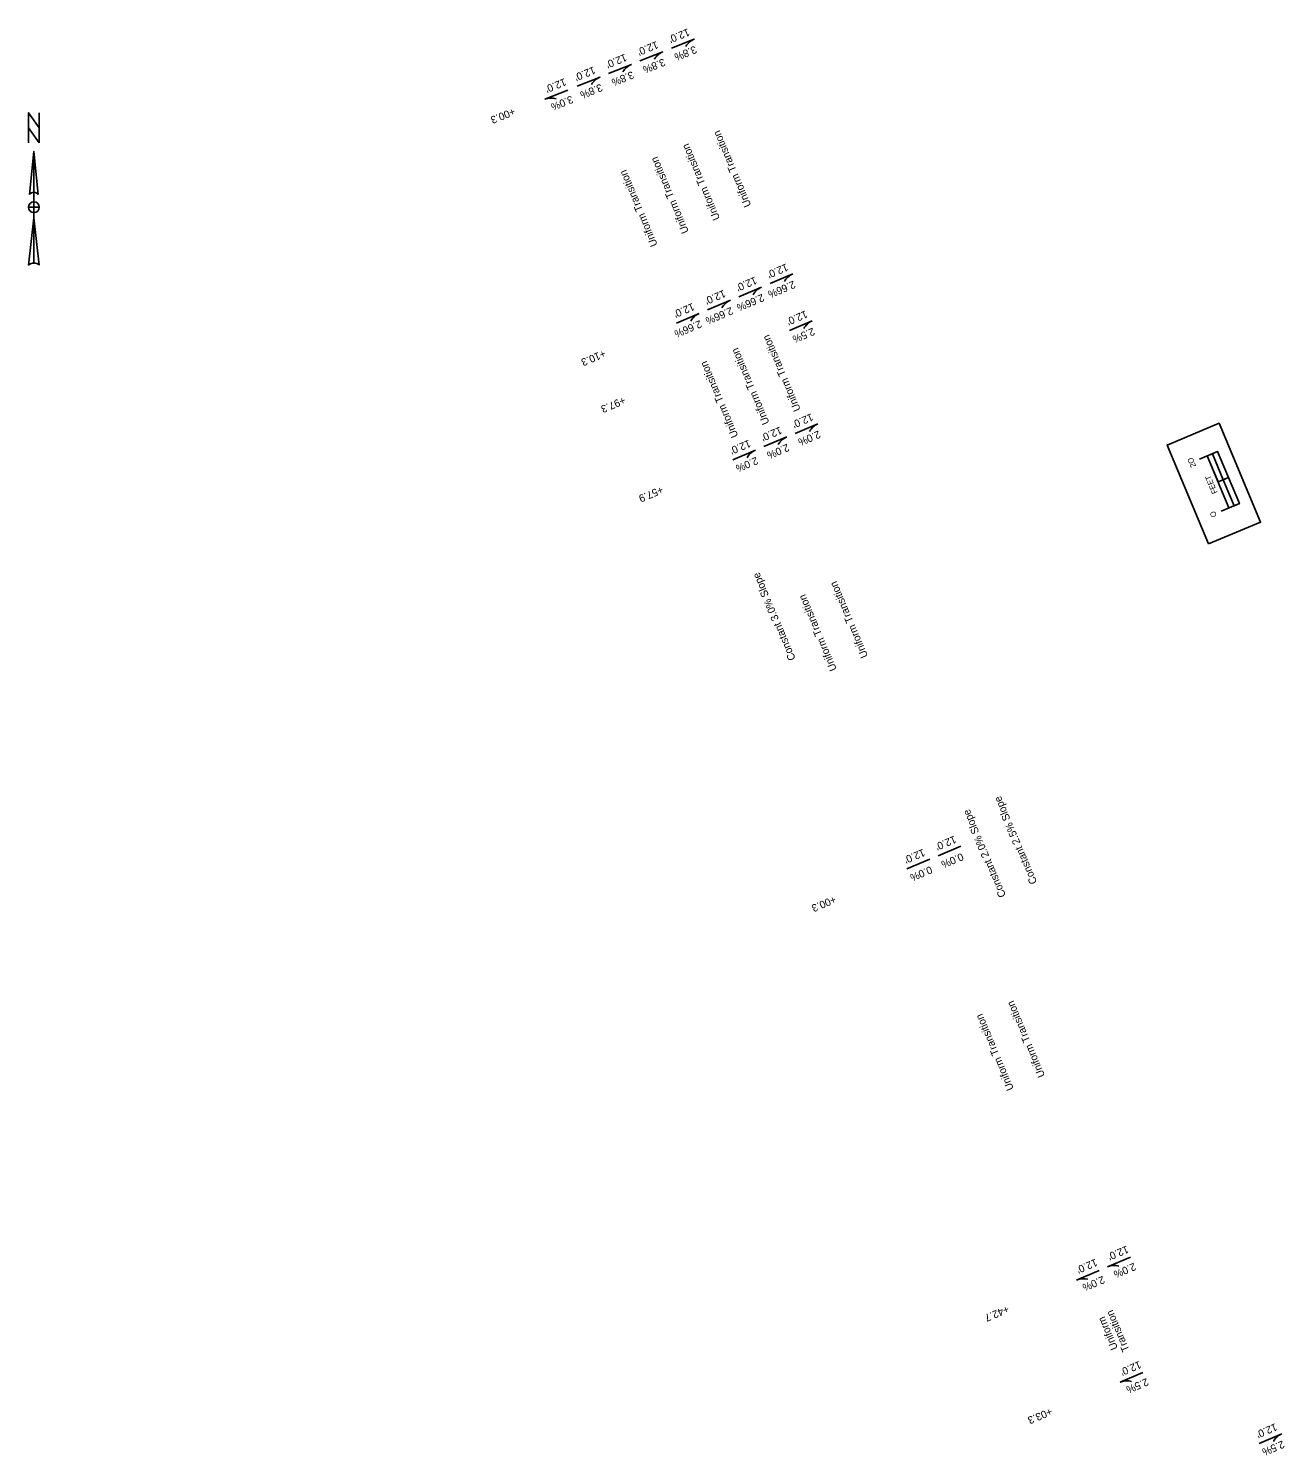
# Model space of a CAD drawing. Extents: x 20505195 to 20506806, y 7965197 to 7979043.
# Drawn here: x 20505639 to 20506084, y 7975959 to 7976464 of the extents above; entities that cross this region are included whole.
import ezdxf

# ---------------------------------------------------------------- set-up
doc = ezdxf.new("R2010")
doc.units = 0
doc.layers.add('Cell', color=7, linetype='Continuous')
doc.layers.add('SheetText', color=7, linetype='Continuous')

msp = doc.modelspace()

# ---------------------------------------------------------------- linework, layer by layer
at = {"layer": 'Cell'}
for p, q in [((20505641.01, 7976420.72), (20505642.53, 7976405.5)), ((20505641.01, 7976420.72), (20505641.01, 7976381.16)), ((20505639.49, 7976405.5), (20505639.49, 7976405.5)), ((20505639.54, 7976405.65), (20505639.83, 7976405.96)), ((20505639.11, 7976380.4), (20505641.01, 7976397.14)), ((20505641.01, 7976399.04), (20505641.01, 7976399.04))]:
    msp.add_line(p, q, dxfattribs=at)
msp.add_lwpolyline([(20505642.91, 7976423.76), (20505639.11, 7976429.08), (20505639.11, 7976434.41), (20505642.91, 7976429.08)], close=True, dxfattribs=at)
for points in [[(20505639.11, 7976423.76), (20505639.11, 7976434.41), (20505642.91, 7976429.08), (20505642.91, 7976434.41)], [(20505639.49, 7976405.5), (20505641.01, 7976420.72), (20505641.01, 7976406.27)], [(20505642.91, 7976400.94), (20505641.01, 7976400.94), (20505641.01, 7976402.84)], [(20505641.01, 7976399.04), (20505641.01, 7976400.94), (20505639.11, 7976400.94)], [(20505641.01, 7976381.16), (20505641.01, 7976397.14), (20505642.91, 7976380.4)]]:
    msp.add_lwpolyline(points, dxfattribs=at)
for centre, radius, start, end in [((20505641.01, 7976400.94), 1.9, 90, 180), ((20505641.01, 7976404.36), 1.9, 90.0204, 143.1257), ((20505641.01, 7976404.36), 1.9, 36.8481, 90.0218), ((20505641.01, 7976400.94), 1.9, 0, 90), ((20505641.01, 7976400.94), 1.9, 180, 270), ((20505641.01, 7976400.94), 1.9, 270, 360), ((20505641.01, 7976378.41), 2.76, 89.9894, 133.619), ((20505641.01, 7976378.41), 2.76, 46.4021, 90.0006)]:
    msp.add_arc(centre, radius, start, end, dxfattribs=at)
at = {"layer": 'SheetText'}
for p, q in [((20505866.88, 7976457.28), (20505875.01, 7976460.56)), ((20505855.75, 7976452.79), (20505863.88, 7976456.07)), ((20505844.62, 7976448.3), (20505852.75, 7976451.58)), ((20505830.2, 7976442.48), (20505822.07, 7976439.19)), ((20505833.49, 7976443.8), (20505841.63, 7976447.09)), ((20505901.83, 7976373.89), (20505909.91, 7976377.3)), ((20505890.77, 7976369.22), (20505898.85, 7976372.63)), ((20505879.72, 7976364.56), (20505887.8, 7976367.97)), ((20505868.66, 7976359.89), (20505876.74, 7976363.3)), ((20505908.7, 7976357.24), (20505916.78, 7976360.65)), ((20505910.71, 7976320.76), (20505918.79, 7976324.17)), ((20505899.66, 7976316.1), (20505907.74, 7976319.51)), ((20505888.6, 7976311.43), (20505896.68, 7976314.84)), ((20506064.28, 7976305.13), (20506060.59, 7976303.59)), ((20506064.28, 7976305.13), (20506060.59, 7976303.59)), ((20505961.4, 7976171.09), (20505969.48, 7976174.5)), ((20505950.34, 7976166.43), (20505958.42, 7976169.84)), ((20506029.53, 7976028.79), (20506021.45, 7976025.38)), ((20506018.47, 7976024.12), (20506010.39, 7976020.71)), ((20506033.98, 7975987.9), (20506025.9, 7975984.49)), ((20506075.11, 7975962.83), (20506083.19, 7975966.24))]:
    msp.add_line(p, q, dxfattribs=at)
for points in [[(20506057.21, 7976281.59), (20506042.57, 7976316.65), (20506061.02, 7976324.36), (20506075.67, 7976289.3)], [(20506057.21, 7976281.59), (20506042.57, 7976316.65), (20506061.02, 7976324.36), (20506075.67, 7976289.3)], [(20506062.43, 7976304.35), (20506058.57, 7976313.58), (20506056.74, 7976312.82), (20506060.59, 7976303.59)], [(20506068.14, 7976295.9), (20506064.28, 7976305.13), (20506062.43, 7976304.35), (20506066.28, 7976295.13)]]:
    msp.add_lwpolyline(points, close=True, dxfattribs=at)
for points in [[(20506061.68, 7976293.21), (20506068.14, 7976295.9), (20506060.43, 7976314.36), (20506053.97, 7976311.66)], [(20506064.45, 7976294.36), (20506056.74, 7976312.82)]]:
    msp.add_lwpolyline(points, dxfattribs=at)
for centre, start, end in [((20505877.32, 7976454.84), 111.9773, 150.1803), ((20505866.19, 7976450.35), 111.9773, 150.1803), ((20505855.06, 7976445.86), 111.9773, 150.1803), ((20505843.93, 7976441.37), 111.9773, 150.1803), ((20505824.38, 7976433.48), 73.7742, 111.9773), ((20505912.31, 7976371.62), 112.8763, 151.0793), ((20505901.25, 7976366.95), 112.8763, 151.0793), ((20505890.19, 7976362.29), 112.8763, 151.0793), ((20505879.14, 7976357.62), 112.8763, 151.0793), ((20505919.18, 7976354.97), 112.8763, 151.0793), ((20505921.19, 7976318.49), 112.8763, 151.0793), ((20505910.13, 7976313.83), 112.8763, 151.0793), ((20505899.08, 7976309.16), 112.8763, 151.0793), ((20506023.85, 7976019.7), 74.6732, 112.8763), ((20506012.79, 7976015.03), 74.6732, 112.8763), ((20506028.3, 7975978.81), 74.6732, 112.8763), ((20506085.59, 7975960.56), 112.8763, 151.0793)]:
    msp.add_arc(centre, 6.16, start, end, dxfattribs=at)

# ---------------------------------------------------------------- texts
for s, height, rotation, p in [("12.0'", 2.664, 202.08, (20505872.72, 7976464.37)), ("12.0'", 2.664, 202.08, (20505861.59, 7976459.88)), ('3.8%', 2.664, 202.08, (20505875.19, 7976458.23)), ("12.0'", 2.664, 202.08, (20505850.46, 7976455.39)), ('3.8%', 2.664, 202.08, (20505864.06, 7976453.74)), ("12.0'", 2.664, 202.08, (20505839.33, 7976450.9)), ('3.8%', 2.664, 202.08, (20505852.94, 7976449.25)), ("12.0'", 2.664, 202.08, (20505828.96, 7976446.71)), ('3.8%', 2.664, 202.08, (20505841.81, 7976444.76)), ('3.0%', 2.664, 202.08, (20505831.44, 7976440.57)), ('+00.3', 2.664, 201.9773, (20505810.92, 7976436.26)), ('Uniform Transition', 2.664, 112.7854, (20505895.23, 7976401.6)), ('Uniform Transition', 2.664, 112.7854, (20505884.17, 7976396.94)), ('Uniform Transition', 2.664, 112.7854, (20505873.11, 7976392.27)), ('Uniform Transition', 2.664, 112.7854, (20505862.06, 7976387.61)), ("12.0'", 2.664, 202.979, (20505907.56, 7976381.07)), ("12.0'", 2.664, 202.979, (20505885.44, 7976371.74)), ("12.0'", 2.664, 202.979, (20505896.5, 7976376.41)), ('2.66%', 2.664, 202.979, (20505910.13, 7976374.97)), ("12.0'", 2.664, 202.979, (20505874.39, 7976367.08)), ('2.66%', 2.664, 202.979, (20505899.07, 7976370.31)), ('2.66%', 2.664, 202.979, (20505888.02, 7976365.64)), ("12.0'", 2.664, 202.979, (20505914.43, 7976364.43)), ('2.66%', 2.664, 202.979, (20505876.96, 7976360.98)), ('2.5%', 2.664, 202.979, (20505917, 7976358.32)), ('Uniform Transition', 2.664, 112.7854, (20505912.75, 7976329.2)), ('+10.3', 2.664, 202.8779, (20505842.95, 7976350.49)), ('Uniform Transition', 2.664, 112.7854, (20505890.64, 7976319.87)), ('Uniform Transition', 2.664, 112.7854, (20505901.69, 7976324.53)), ('+97.3', 2.664, 202.8779, (20505849.95, 7976333.9)), ("12.0'", 2.664, 202.979, (20505916.44, 7976327.95)), ("12.0'", 2.664, 202.979, (20505905.38, 7976323.28)), ('2.0%', 2.664, 202.979, (20505919.01, 7976321.85)), ("12.0'", 2.664, 202.979, (20505894.33, 7976318.62)), ('2.0%', 2.664, 202.979, (20505907.96, 7976317.18)), ('2.0%', 2.664, 202.979, (20505896.9, 7976312.52)), ('2O', 2, 112.6732, (20506052.85, 7976309.16)), ('+57.9', 2.664, 202.8779, (20505863.35, 7976302.22)), ('FEET', 2, 112.6732, (20506060.42, 7976299.85)), ('O', 2, 112.6732, (20506060.21, 7976291.53)), ('Constant 3.0% Slope', 2.664, 112.8763, (20505910.98, 7976240.93)), ('Uniform Transition', 2.664, 112.7854, (20505936.6, 7976241.82)), ('Uniform Transition', 2.664, 112.7854, (20505925.53, 7976237.17)), ('Constant 2.5% Slope', 2.664, 112.8763, (20505996.53, 7976161.65)), ('Constant 2.0% Slope', 2.664, 112.8763, (20505985.48, 7976156.98)), ("12.0'", 2.664, 202.979, (20505967.13, 7976178.28)), ("12.0'", 2.664, 202.979, (20505956.07, 7976173.62)), ('0.0%', 2.664, 202.979, (20505969.7, 7976172.18)), ('0.0%', 2.664, 202.979, (20505958.64, 7976167.51)), ('+00.3', 2.664, 202.8779, (20505924.59, 7976157.01)), ('Uniform Transition', 2.664, 112.7854, (20505999.32, 7976093.15)), ('Uniform Transition', 2.664, 112.7854, (20505988.26, 7976088.51)), ("12.0'", 2.664, 202.979, (20506028.22, 7976033)), ("12.0'", 2.664, 202.979, (20506017.16, 7976028.34)), ('2.0%', 2.664, 202.979, (20506030.79, 7976026.9)), ('2.0%', 2.664, 202.979, (20506019.74, 7976022.24)), ('+42.7', 2.664, 202.8779, (20505985.86, 7976011.81)), ('Uniform', 2.664, 112.7854, (20506025.15, 7975996.56)), ('Transition', 2.664, 112.7854, (20506029.26, 7975995.92)), ("12.0'", 2.664, 202.979, (20506032.67, 7975992.12)), ('2.5%', 2.664, 202.979, (20506035.24, 7975986.02)), ('+03.3', 2.664, 202.8779, (20506001.18, 7975975.51)), ("12.0'", 2.664, 202.979, (20506080.84, 7975970.02)), ('2.5%', 2.664, 202.979, (20506083.41, 7975963.92))]:
    msp.add_text(s, height=height, rotation=rotation, dxfattribs=at).set_placement(p)

doc.saveas('drawing.dxf')
